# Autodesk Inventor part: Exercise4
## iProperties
Created: 2002-02
Part Number: Exercise4
Document SubType Name: Modeling
Control State: 0
Master: False
Checked Out: False
Shininess: 64.0
Length Units: 11269
Angle Units: 11279
Time Units: 11290
Mass Units: 11283
Length Display Precision: 3
Angle Display Precision: 2
Compacted: True
Density: 0.0
Volumn: 0.0
Area: 0.0
PropertySet Name: Model Information
